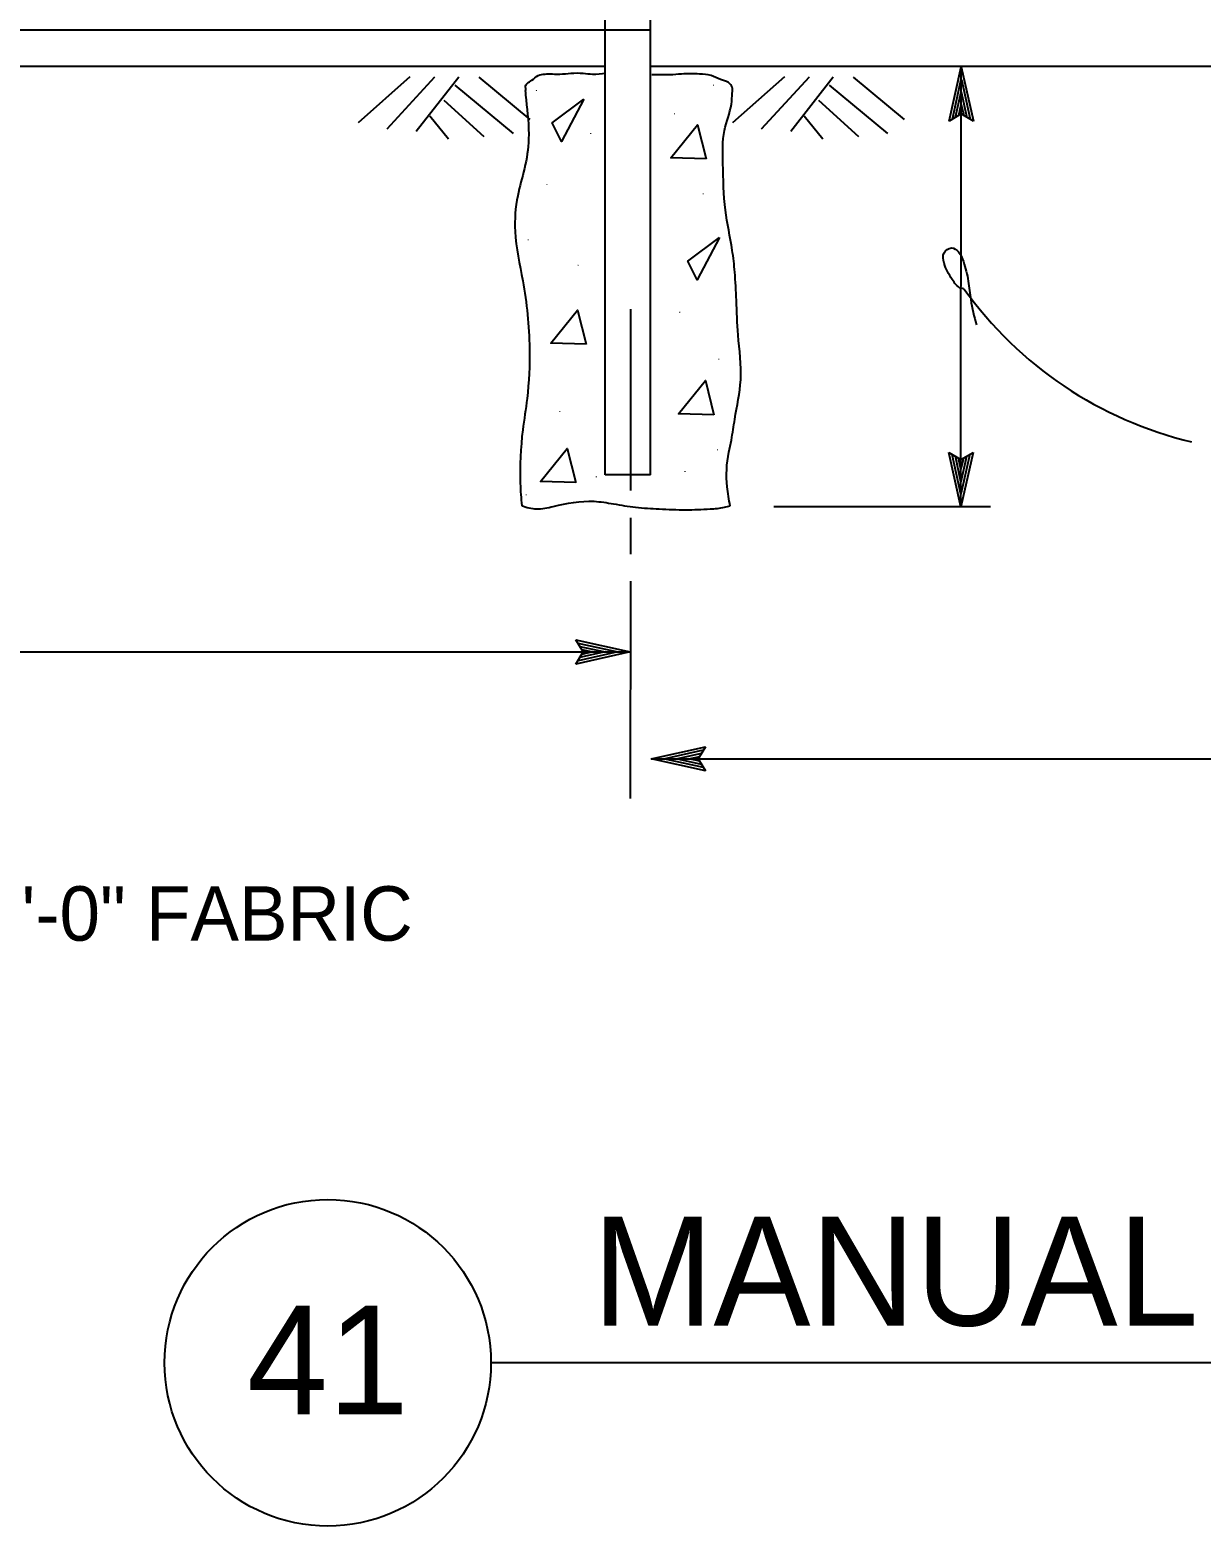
# Model space of a CAD drawing. Extents: x -121933 to -117742, y -103160 to -100084.
# Drawn here: x -121289.1 to -121160, y -102542.1 to -102377.2 of the extents above; entities that cross this region are included whole.
import ezdxf

# ---------------------------------------------------------------- set-up
doc = ezdxf.new("R2010")
doc.units = 0
for name, color, linetype in [('G-MARK', 7, 'Continuous'), ('G-TEXT', 7, 'Continuous'), ('Misc CnstDet(22)', 7, 'Continuous'), ('Nongeo Data(60)', 7, 'Continuous')]:
    doc.layers.add(name, color=color, linetype=linetype)

msp = doc.modelspace()

# ---------------------------------------------------------------- linework, layer by layer
at = {"layer": 'G-MARK'}
for p, q in [((-121186.45, -102429.78), (-121186.4, -102381.27)), ((-121207.07, -102429.76), (-121183.19, -102429.76)), ((-121399.81, -102445.78), (-121222.92, -102445.78)), ((-121220.62, -102457.55), (-120808.19, -102457.55))]:
    msp.add_line(p, q, dxfattribs=at)
for points in [[(-121222.88, -102407.98), (-121222.9, -102427.98)], [(-121222.9, -102430.98), (-121222.9, -102434.98)], [(-121222.91, -102437.98), (-121222.93, -102461.92)]]:
    msp.add_lwpolyline(points, dxfattribs=at)
msp.add_arc((-121151.06, -102380.7), 43.08, 215.5482, 256.6593, dxfattribs=at)
msp.add_spline([(-121186.11, -102405.74), (-121186.43, -102405.69), (-121187.41, -102404.71), (-121188.3, -102402.93), (-121188.3, -102401.77), (-121187.5, -102401.24), (-121186.7, -102401.68), (-121186.17, -102402.75), (-121185.63, -102404.89), (-121185.37, -102406.94), (-121184.74, -102409.7)], degree=3, dxfattribs=at)
at = {"layer": 'G-TEXT'}
for p, q in [((-121187.74, -102387.27), (-121186.4, -102381.27)), ((-121186.4, -102381.27), (-121186.4, -102381.27)), ((-121186.4, -102381.27), (-121185.07, -102387.27)), ((-121187.39, -102387.05), (-121186.4, -102382.65)), ((-121186.39, -102382.66), (-121185.43, -102387.03)), ((-121187.03, -102386.82), (-121186.4, -102384.03)), ((-121186.4, -102384.03), (-121185.78, -102386.86)), ((-121186.4, -102386.47), (-121187.74, -102387.27)), ((-121186.68, -102386.64), (-121186.4, -102385.41)), ((-121186.4, -102385.41), (-121186.14, -102386.62)), ((-121185.07, -102387.27), (-121186.4, -102386.47)), ((-121187.74, -102387.27), (-121187.74, -102387.27)), ((-121185.07, -102387.27), (-121185.07, -102387.27)), ((-121186.45, -102429.78), (-121187.77, -102423.78)), ((-121187.77, -102423.78), (-121187.77, -102423.78)), ((-121187.77, -102423.78), (-121186.44, -102424.58)), ((-121186.45, -102428.39), (-121187.41, -102424.01)), ((-121186.44, -102427.01), (-121187.06, -102424.19)), ((-121186.44, -102425.63), (-121186.7, -102424.42)), ((-121185.1, -102423.78), (-121186.45, -102429.78)), ((-121186.44, -102424.58), (-121185.1, -102423.78)), ((-121185.46, -102423.99), (-121186.44, -102428.4)), ((-121185.82, -102424.23), (-121186.44, -102427.01)), ((-121186.16, -102424.4), (-121186.44, -102425.63)), ((-121185.1, -102423.78), (-121185.1, -102423.78)), ((-121186.45, -102429.78), (-121186.45, -102429.78)), ((-121228.12, -102445.78), (-121228.92, -102444.44)), ((-121228.92, -102444.44), (-121228.92, -102444.44)), ((-121228.92, -102444.44), (-121222.92, -102445.78)), ((-121222.92, -102445.78), (-121228.92, -102447.11)), ((-121228.92, -102447.11), (-121228.12, -102445.78)), ((-121228.7, -102444.8), (-121224.3, -102445.78)), ((-121224.31, -102445.78), (-121228.68, -102446.75)), ((-121225.68, -102445.78), (-121228.51, -102446.4)), ((-121228.47, -102445.16), (-121225.68, -102445.78)), ((-121228.29, -102445.5), (-121227.06, -102445.78)), ((-121227.06, -102445.78), (-121228.27, -102446.05)), ((-121222.92, -102445.78), (-121222.92, -102445.78)), ((-121228.92, -102447.11), (-121228.92, -102447.11)), ((-121220.62, -102457.55), (-121214.62, -102456.22)), ((-121214.62, -102458.89), (-121220.62, -102457.55)), ((-121220.62, -102457.55), (-121220.62, -102457.55)), ((-121214.83, -102458.53), (-121219.24, -102457.55)), ((-121219.23, -102457.55), (-121214.85, -102456.58)), ((-121217.85, -102457.55), (-121215.03, -102456.93)), ((-121215.07, -102458.17), (-121217.85, -102457.55)), ((-121216.47, -102457.55), (-121215.26, -102457.29)), ((-121215.24, -102457.83), (-121216.47, -102457.55)), ((-121214.62, -102456.22), (-121215.42, -102457.55)), ((-121215.42, -102457.55), (-121214.62, -102458.89)), ((-121214.62, -102456.22), (-121214.62, -102456.22)), ((-121214.62, -102458.89), (-121214.62, -102458.89))]:
    msp.add_line(p, q, dxfattribs=at)
at = {"layer": 'Misc CnstDet(22)'}
msp.add_line((-120905.86, -102524.14), (-121238.29, -102524.14), dxfattribs=at)
msp.add_circle((-121256.29, -102524.14), 18, dxfattribs=at)
at = {"layer": 'Nongeo Data(60)'}
for p, q in [((-121225.7, -102426.24), (-121225.7, -102366.89)), ((-121220.7, -102426.24), (-121220.7, -102366.89)), ((-121220.7, -102377.24), (-121396.06, -102377.24)), ((-121225.7, -102381.24), (-121397.7, -102381.24)), ((-121018.08, -102381.24), (-121220.7, -102381.24)), ((-121247.24, -102382.37), (-121252.94, -102387.44)), ((-121244.5, -102382.41), (-121249.79, -102388.16)), ((-121241.83, -102382.41), (-121246.53, -102388.39)), ((-121242.29, -102383.3), (-121235.85, -102388.61)), ((-121239.63, -102382.43), (-121234, -102387.07)), ((-121205.92, -102382.37), (-121211.63, -102387.44)), ((-121203.18, -102382.41), (-121208.48, -102388.16)), ((-121200.52, -102382.41), (-121205.22, -102388.39)), ((-121200.98, -102383.3), (-121194.54, -102388.61)), ((-121198.32, -102382.43), (-121192.69, -102387.07)), ((-121243.47, -102384.95), (-121239.07, -102388.96)), ((-121202.16, -102384.95), (-121197.76, -102388.96)), ((-121245.03, -102386.67), (-121242.97, -102389.2)), ((-121203.72, -102386.67), (-121201.66, -102389.2)), ((-121220.7, -102426.24), (-121225.7, -102426.24)), ((-121220.7, -102426.24), (-121225.7, -102426.24)), ((-121220.7, -102426.24), (-121225.7, -102426.24))]:
    msp.add_line(p, q, dxfattribs=at)
for points in [[(-121228.03, -102384.85), (-121230.5, -102389.5), (-121231.53, -102387.43)], [(-121214.55, -102391.43), (-121218.45, -102391.32), (-121215.5, -102387.66)], [(-121213.08, -102400.1), (-121215.55, -102404.75), (-121216.57, -102402.68)], [(-121227.78, -102411.86), (-121231.68, -102411.75), (-121228.73, -102408.09)], [(-121213.69, -102419.63), (-121217.59, -102419.52), (-121214.63, -102415.86)], [(-121228.93, -102427.11), (-121232.83, -102427), (-121229.88, -102423.34)]]:
    msp.add_lwpolyline(points, close=True, dxfattribs=at)
for points in [[(-121234.51, -102383.88), (-121234.47, -102383.88), (-121234.47, -102383.53), (-121234.29, -102383.1), (-121233.78, -102382.76), (-121233.09, -102382.24), (-121232.32, -102382.07), (-121230.68, -102382.07), (-121229.48, -102381.98), (-121228.1, -102381.98), (-121227.07, -102382.07), (-121225.61, -102381.98)], [(-121211.68, -102384.14), (-121211.67, -102383.53), (-121212.1, -102383.02), (-121212.96, -102382.67), (-121214, -102382.24), (-121215.29, -102382.07), (-121217.26, -102382.07), (-121218.55, -102382.16), (-121219.93, -102382.16), (-121220.53, -102382.16)], [(-121234.51, -102383.88), (-121234.41, -102384.92), (-121234.13, -102389.22), (-121234.59, -102392.5), (-121235.34, -102395.49), (-121235.62, -102399.42), (-121234.78, -102404.85), (-121234.03, -102412.33), (-121234.31, -102417.85), (-121234.78, -102421.31), (-121235.06, -102427.21), (-121234.9, -102429.66)], [(-121211.9, -102429.66), (-121212.24, -102427.58), (-121212.05, -102423.75), (-121211.77, -102422.44), (-121211.39, -102420.1), (-121210.74, -102415.79), (-121211.02, -102410.84), (-121211.21, -102407), (-121211.39, -102403.91), (-121211.67, -102401.48), (-121212.42, -102397.08), (-121212.7, -102391.94), (-121212.52, -102388.29), (-121211.77, -102385.39), (-121211.68, -102384.14)], [(-121234.9, -102429.66), (-121233.28, -102430.01), (-121231.41, -102429.73), (-121226.92, -102429.17), (-121224.77, -102429.45), (-121222.34, -102429.83), (-121219.72, -102430.01), (-121216.82, -102430.11), (-121214.11, -102430.01), (-121212.52, -102429.83), (-121211.9, -102429.66)]]:
    msp.add_spline(points, degree=3, dxfattribs=at)

# ---------------------------------------------------------------- texts
at = {"layer": 'Misc CnstDet(22)'}
for s, height, p in [('TYPE CL-6 = 6\'-0" FABRIC', 6, (-121344.26, -102477.61)), ('MANUAL DOUBLE SWING GATE', 12, (-121227.11, -102520.04)), ('41', 12, (-121265.19, -102529.84))]:
    msp.add_text(s, height=height, dxfattribs=at).set_placement(p)
at = {"layer": 'Nongeo Data(60)'}
for p in [(-121213.8, -102383.15), (-121233.33, -102383.72), (-121218.09, -102386.31), (-121227.34, -102388.46), (-121232.18, -102394.08), (-121214.93, -102395.12), (-121234.23, -102400.2), (-121228.73, -102403), (-121217.52, -102408.18), (-121213.2, -102413.36), (-121230.75, -102419.11), (-121213.35, -102423.34), (-121226.72, -102426.31), (-121216.94, -102425.73), (-121234.45, -102428.3)]:
    msp.add_text('.', height=0.8, rotation=266.9315, dxfattribs=at).set_placement(p)

doc.saveas('drawing.dxf')
